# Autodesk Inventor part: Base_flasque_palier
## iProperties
Shininess: 64.0
Length Units: 11269
Angle Units: 11279
Time Units: 11290
Mass Units: 11283
Length Display Precision: 3
Angle Display Precision: 2
Compacted: True
Part Number: Base_flasque_palier
Document SubType Name: Modeling
Created: 2008-02
Material: Acier inoxydable, austénitique
Designer: Pascal
Density: 0.0
Volumn: 0.0
Area: 0.0
PropertySet Name: Model Information
Control State: 0
Master: False
Checked Out: False
MATIERE_PIECE: X2CrNi1811
OBSERVATIONS: Ø715 ep.20
DESIGNATION: Base flasque palier
Author: Pascal
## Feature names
1. Extrusion1
2. Extrusion2
3. Réseau circulaire1 [Circular Pattern]
4. Extrusion3
5. Extrusion4
6. Extrusion5
